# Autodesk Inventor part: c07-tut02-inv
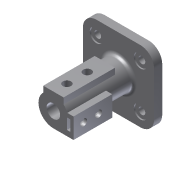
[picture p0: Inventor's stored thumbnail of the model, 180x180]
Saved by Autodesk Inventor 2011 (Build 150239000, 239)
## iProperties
Created: 2010-03
Part Number: c07-tut02-inv
Document SubType Name: Modeling
Designer: CADSoft
Density: 1 g/cm^3
Author: CADSoft
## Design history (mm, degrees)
sketch "Sketch1"
  geometry: 1 further point
sketch "Sketch2"
  geometry: L1 (32.5, 52.5)-(-32.5, 52.5); L2 (-52.5, 32.5)-(-52.5, -32.5); L3 (-32.5, -52.5)-(32.5, -52.5); L4 (52.5, -32.5)-(52.5, 32.5); A1 r 20 centre (32.5, 32.5) between (52.5, 32.5) and (32.5, 52.5); A2 r 20 centre (-32.5, 32.5) between (-32.5, 52.5) and (-52.5, 32.5); A3 r 20 centre (-32.5, -32.5) between (-52.5, -32.5) and (-32.5, -52.5); A4 r 20 centre (32.5, -32.5) between (32.5, -52.5) and (52.5, -32.5); 4 further points
  constraints: 8 end point, 8 point on circle, 8 tangent, 6 point on line, 4 centre point, 3 equal radius, 3 perpendicular, 1 other
  dimensions: "d3" = 105 distance of point (52.5, 52.5) point (-52.5, 52.5); "d4" = 105 distance of point (52.5, -52.5) point (52.5, 52.5); "d6" = 52.5 distance from line of L1 point (0, 0); "d7" = 52.5 distance from line of L4 point (0, 0); "d8" = 20 radius of A1
extrude "Extrusion1" new body sketch "Sketch2" distance "d9" = 12; taper "d10" = 0 deg
hole "Hole1" diameter "d13" = 10; stored, may be unused: countersink angle "d17" = 90 deg, drill point angle "d19" = 118 deg; dims "d11" = 10, "d12" = 10, "d14" = 6, "d15" = 20, "d16" = 2, "d18" = 8
hole "Hole2" diameter "d22" = 10; stored, may be unused: countersink angle "d26" = 90 deg, drill point angle "d28" = 118 deg; dims "d20" = 10, "d21" = 10, "d23" = 6, "d24" = 20, "d25" = 2, "d27" = 8
hole "Hole3" diameter "d31" = 10; stored, may be unused: countersink angle "d35" = 90 deg, drill point angle "d37" = 118 deg; dims "d29" = 10, "d30" = 10, "d32" = 6, "d33" = 20, "d34" = 2, "d36" = 8
hole "Hole4" diameter "d40" = 10; stored, may be unused: countersink angle "d44" = 90 deg, drill point angle "d46" = 118 deg; dims "d38" = 10, "d39" = 10, "d41" = 6, "d42" = 20, "d43" = 2, "d45" = 8
sketch "Sketch3"
  geometry: C1 r 22 at (0, 0); 1 further point
  constraints: 1 centre point, 1 coincident
  dimensions: "d47" = 44 diameter of C1
extrude "Extrusion2" join sketch "Sketch3" distance "d48" = 96; taper "d49" = 0 deg
sketch "Sketch4"
  geometry: L1 (-15, 25)-(15, 25); L2 (15, 25)-(15, 16.093); L3 (-14.745, 16.328)-(-15, 16.093); L4 (-15, 16.093)-(-15, 25); A1 r 22 centre (0, 0) between (15, 16.093) and (-15, 16.093); 1 further point
  constraints: 8 end point, 4 point on circle, 2 vertical, 1 centre point, 1 coincident
  dimensions: "d50" = 30 distance of L1.start L1.end; "d52" = 15 distance from line of point (0, 0) L4; "d53" = 25 distance from line of point (0, 0) L1
extrude "Extrusion3" join sketch "Sketch4" distance "d54" = 76; taper "d55" = 0 deg
sketch "Sketch5"
  geometry: L1 (0, -22)-(29.709, -22); L2 (29.709, -22)-(29.709, 8); L3 (29.709, 8)-(20.494, 8); A1 r 22 centre (0, 0) between (0, -22) and (20.494, 8); 1 further point
  constraints: 6 end point, 2 point on circle, 1 centre point, 1 coincident
  dimensions: "d61" = 30 distance of L1.end L2.end
extrude "Extrusion4" join sketch "Sketch5" distance "d62" = 57; taper "d63" = 0 deg
sketch "Sketch6"
  geometry: L1 (20, 2)-(25, 2); L2 (25, 2)-(25, -14); L3 (25, -14)-(20, -14); L4 (20, -14)-(20, 2); A1 r 22 centre (0, 0) between (20.494, 8) and (15, 16.093) reference
  constraints: 8 end point
  dimensions: "d64" = 2 distance from line of A1.centre L1; "d66" = 25 distance from line of L2 A1.centre; "d67" = 5 distance of L2.end L3.end; "d68" = 16 distance of L1.end L2.end
extrude "Extrusion5" cut sketch "Sketch6" distance "d69" = 50; taper "d70" = 0 deg
hole "Hole5" diameter "d73" = 20; stored, may be unused: countersink angle "d77" = 90 deg, drill point angle "d79" = 0 deg; dims "d71" = 10, "d72" = 10, "d74" = 6, "d75" = 20, "d76" = 2, "d78" = 96
hole "Hole6" diameter "d82" = 12; stored, may be unused: countersink angle "d86" = 90 deg, drill point angle "d88" = 118 deg; dims "d80" = 20, "d81" = 15, "d83" = 6, "d84" = 20, "d85" = 2, "d87" = 96
hole "Hole7" diameter "d91" = 12; stored, may be unused: countersink angle "d95" = 90 deg, drill point angle "d97" = 118 deg; dims "d89" = 15, "d90" = 50, "d92" = 6, "d93" = 20, "d94" = 2, "d96" = 96
hole "Hole8" diameter "d100" = 10; stored, may be unused: countersink angle "d104" = 90 deg, drill point angle "d106" = 118 deg; dims "d98" = 15, "d99" = 15, "d101" = 6, "d102" = 20, "d103" = 2, "d105" = 96
hole "Hole9" diameter "d109" = 10; stored, may be unused: countersink angle "d113" = 90 deg, drill point angle "d115" = 118 deg; dims "d107" = 15, "d108" = 37, "d110" = 6, "d111" = 20, "d112" = 2, "d114" = 96
fillet "Fillet1" dims "d116" = 5
body "Solid1"
